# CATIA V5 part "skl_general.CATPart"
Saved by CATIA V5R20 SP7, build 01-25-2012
Part number: skl_general
Publications: "point A", "point B", "point C", "point D", "point E", "point F", "point G", "point H"
Bounding box of the stored display mesh (mm): x 0 to 0, y 0 to 2.4, z -1 to 2.63
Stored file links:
  U:\IAO\skl_general.CATPart
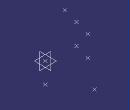
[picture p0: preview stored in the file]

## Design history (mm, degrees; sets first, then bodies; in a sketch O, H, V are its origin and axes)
Set1
  Point1 "point A": type OnPlane, Support yz-plane, H 0, V 0, Direction (0, 1, 0)
  Point2 "point B": type OnPlane, Support yz-plane, H 2.07, V 2.17, Direction (0, 1, 0)
  Point3 "point C": type OnPlane, Support yz-plane, H 0.96, V 2.63, Direction (0, 1, 0)
  Point4 "point D": type OnPlane, Support yz-plane, H 2.4, V 0, Direction (0, 1, 0)
  Point5 "point E": type OnPlane, Support yz-plane, H 1.52, V 2.4, Direction (0, 1, 0)
  Point6 "point F": type OnPlane, Support yz-plane, H 1.52, V 1.4, Direction (0, 1, 0)
  Point7 "point G": type OnPlane, Support yz-plane, H 2.08, V 1.17, Direction (0, 1, 0)
  Point8 "point H": type OnPlane, Support yz-plane, H 0, V -1, Direction (0, 1, 0)
Body1 (main body)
